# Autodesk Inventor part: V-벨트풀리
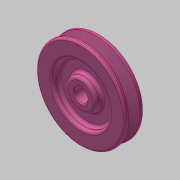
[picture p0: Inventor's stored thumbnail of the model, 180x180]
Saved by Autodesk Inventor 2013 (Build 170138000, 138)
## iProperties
Created: 2020-05
Part Number: V-벨트풀리
Material: 알루미늄 6061
Document SubType Name: Modeling
Designer: mduedu
Density: 1 g/cm^3
Author: mduedu
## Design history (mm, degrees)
sketch "스케치1"
  geometry: L1 (-10, 0)-(10, 0); L2 (10, 47.5)-(-10, 47.5); L3 (-5.976, 47.5)-(-2.154, 35); L4 (-2.154, 35)-(2.154, 35); L5 (2.154, 35)-(5.976, 47.5); L6 (0, 0)-(0, 47.5); L7 (-10, 30)-(-3, 30); L8 (-3, 30)-(-3, 16); L9 (-3, 16)-(-10, 16); L10 (-10, 47.5)-(-10, 30); L11 (-10, 16)-(-10, 0); L12 (10, 30)-(3, 30); L13 (3, 30)-(3, 16); L14 (3, 16)-(10, 16); L15 (10, 0)-(10, 16); L16 (10, 30)-(10, 47.5); L17 (-4.6, 43)-(4.6, 43); 2 further points
  constraints: 34 end point, 6 parallel, 6 perpendicular, 4 point on line, 4 symmetric about line, 3 midpoint, 2 horizontal, 1 coincident, 1 collinear, 1 equal length, 1 vertical alignment
  dimensions: "d0" = 95 diameter of L2 L1; "d2" = 20 distance between parallel lines of L16 L10; "d3" = 6 distance between parallel lines of L13 L8; "d4" = 32 diameter of L14 L1; "d5" = 60 diameter of L12 L1; "d6" = 4.5 distance between parallel lines of L17 L2; "d7" = 8 distance between parallel lines of L4 L17; "d8" = 34 deg angle of L5 L3; "d9" = 9.2 distance of L17.start L17.end
revolve "회전1" sketch "스케치1" stored, may be unused: angle "d10" = 90 deg
sketch "스케치2"
  geometry: L1 (-2.5, 6.538)-(2.5, 6.538); L2 (2.5, 6.538)-(2.5, 9.3); L3 (2.5, 9.3)-(-2.5, 9.3); L4 (-2.5, 9.3)-(-2.5, 6.538); A1 r 7 centre (0, 0) between (-2.5, 6.538) and (2.5, 6.538); 1 further point
  constraints: 8 end point, 2 parallel, 2 point on circle, 1 centre point, 1 coincident, 1 horizontal, 1 perpendicular
  dimensions: "d11" = 14 diameter of A1; "d13" = 16.3 dimension on A1 L3; "d14" = 5 distance of L2.end L3.end
extrude "돌출1" cut sketch "스케치2" stored distance "d15" = 10; taper "d16" = 0 deg
chamfer "모따기1" distance "d17" = 1; stored, may be unused: second distance "d18" = 2, angle "d19" = 45 deg
fillet "모깎기1" dims "d20" = 3
fillet "모깎기2" dims "d21" = 2
fillet "모깎기3" dims "d22" = 1
fillet "모깎기4" dims "d23" = 0.5
fillet "모깎기5" dims "d24" = 3
node "솔리드1"
